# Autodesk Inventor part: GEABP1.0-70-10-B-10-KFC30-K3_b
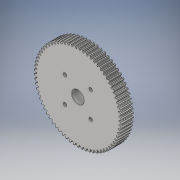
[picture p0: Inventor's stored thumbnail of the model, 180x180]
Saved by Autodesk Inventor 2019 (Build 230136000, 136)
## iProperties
Created: 2022-11
Part Number: GEABP1.0-70-10-B-10-KFC30-K3_b
Material: Generic
Catalog Web Link: www.cadenas.de
Description: GEABM, GEABMS, GEABMT, GEABP, GEABPS, GEABPT, GEABA, GEABAS, GEABAT_body-Plastic Spur Gears - Pressure Angle 20 Degrees, Module 0.5/0.8/1.0/1.5/2.0/2.5/3.0
Vendor: MISUMI
Document SubType Name: Modeling
Designer: psAdmin
Manufacturer: MISUMI
Mass: 48.5724 g
Surface Area: 144.734 cm^2
Volume: 48.5724 cm^3
Density: 1 g/cm^3
Appearance: PSOLRGB-175-175-175
Category: PARTsolutions
Company: MISUMI
Title: GEABP1.0-70-10-B-10-KFC30-K3
Author: Cadenas PARTsolutions
Comments: Plastic Spur Gears - Pressure Angle 20 Degrees, Module 0.5/0.8/1.0/1.5/2.0/2.5/3.0
PSOL_IDENT_0: {$CADENAS_DATA/23d-libs/misumi/metric/54_spur_gears/geabms20/geabms20.prj},408 {VTYP=3D},{NB=GEABP1.
PSOL_IDENT_1: 0-70-10-B-10-KFC30-K3_b},{LINA=GEABP1.0-70-10-B-10-KFC30-K3},{NN=GEABM, GEABMS, GEABMT, GEABP, GEABP
PSOL_IDENT_2: S, GEABPT, GEABA, GEABAS, GEABAT_body},{DATE=17.10.2022 23:48:33},{GEOMDATE=14.09.2022 05:11:00},{VE
PSOL_IDENT_3: RSION=},{LINEID=30},{WBVAR=MATSG,MATCR,NT,B,TS,PS,ALT1,ALT2,TPC,ALT11,ALT10,BS,ALT3,Z,J,ALT4,Q,R,S,T
PSOL_IDENT_4: ,ALT5,LFC,LTC,MALT5,ALT6,KFC,KTC,K},{WBNUMERIC=NT,B,BS,Z,J,Q,R,S,T,LFC,LTC,KFC,KTC,K}  {NB=GEABP1.0-
PSOL_IDENT_5: 70-10-B-10-KFC30-K3_b},{LINA=GEABP1.0-70-10-B-10-KFC30-K3},{KT=DUMMY},{PN=GEABP1.0-70-10-B-10-KFC30-
PSOL_IDENT_6: K3},{TYPE=GEABP},{MATSG=PW},{MATSGALG='MCN','MC Nylon','PW','Polyacetal White','PB','Polyacetal Blue'
PSOL_IDENT_7: },{MATCR=},{MATCRALG='','-','S45C','1045 Carbon Steel','SUS304','304 Stainless Steel'},{MOD=1.0},{MO
PSOL_IDENT_8: D1=1.0},{NT=70},{NTALG=15,16,18,20,22,24,25,26,28,30,32,35,36,40,45,48,50,55,60,70,75,80,90,100,120}
PSOL_IDENT_9: ,{B=10},{BALG=10,15},{TS=B},{TSALG='A','A','B','B'},{TSPN=-B},{PS=10},{PSALG='10','10','11','11','12'
PSOL_IDENT_10: ,'12','13','13','14','14','15','15','16','16','17','17','18','18','19','19','20','20','21','21','22'
PSOL_IDENT_11: ,'22','23','23','24','24','25','25','26','26','27','27','28','28'},{PSCRL='10','10','11','11','12','
PSOL_IDENT_12: 12','13','13','14','14','15','15','16','16','17','17','18','18','19','19','20','20','21','21','22','
PSOL_IDENT_13: 22','23','23','24','24','25','25','26','26','27','27','28','28'},{PSCRW='10','10','12','12','15','15'
PSOL_IDENT_14: ,'20','20'},{DD=70.0},{DD05=35},{DD08=56},{DD10=70},{DD15=105},{DD20=0},{DD25=0},{DD30=0},{D=72.0},{
PSOL_IDENT_15: D05=36},{D08=57.6},{D10=72},{D15=108},{D20=0},{D25=0},{D30=0},{G=67.50},{G05=33.75},{G08=54},{G10=67
PSOL_IDENT_16: .5},{G15=101.25},{G20=0},{G25=0},{G30=0},{H=40.0},{L=20},{LL1=10},{LL2=4.0},{M=M4},{M3D=4},{P=10.00}
PSOL_IDENT_17: ,{DD1=0},{CIFR=15},{CIFM=4},{CIFK=0},{CIFTAP=1},{ALT1=},{ALT1ALG='','w/o Set Screw','KC90','with KC9
PSOL_IDENT_18: 0 (Set Screw)','KC120','with KC120 (Set Screw)'},{ALT1PN=},{ALT2=},{ALT2ALG='','w/o TPC (Tapped Hole
PSOL_IDENT_19: Dimension)','TPC','with TPC (Tapped Hole Dimension)'},{TPC=N/A},{TPCALG='N/A'},{ALT2PN=},{KC=0},{AL
PSOL_IDENT_20: T11=},{ALT11ALG='', 'w/o GBA (Gear bottom adjustment of phase focus)', 'GBA', 'with GBA (Gear bottom
PSOL_IDENT_21: adjustment of phase focus)' },{ALT11PN=},{DEG=0},{ALT10=},{ALT10ALG= '','w/o BS (Boss Cut)','BS','w
PSOL_IDENT_22: ith BS (Boss Cut)' },{ALT10PN=},{BS=0.0},{BSALG=0},{BSMIN=7},{BSMINALG=7.000},{BSMAX=10},{LL13D=10},
PSOL_IDENT_23: {LL23D=16},{LBS=20},{ALT3=},{ALT3ALG= '','w/o Stepped Hole','DHL','with DHL (Stepped Hole)','DHR','w
PSOL_IDENT_24: ith DHR (Stepped Hole)' },{ALT3PN=},{ZJPN=},{ALT31=1},{ALT32=1},{Z=0},{ZALG=0},{ZMINL=12},{ZMAXL=63}
PSOL_IDENT_25: ,{ZMINR=12},{ZMAXR=36},{ZPN=},{J=0.0},{JALG=0},{JMIN=2},{JMAX=0},{JPN=},{ALT4=},{ALT4ALG= '','w/o WD
PSOL_IDENT_26: H (Both Ends Stepped Hole)','WDH','with WDH (Both Ends Stepped Hole)' },{ALT4PN=},{QRSTPN=},{LB=20.0
PSOL_IDENT_27: 00},{Q=0},{QALG=0},{QMIN=12},{QMAX=36},{QPN=},{R=0},{RALG=0},{RMIN=12},{RMAX=36},{RPN=},{S=0},{SALG=
PSOL_IDENT_28: 0},{SMIN=3},{SMAX=14},{SPN=},{T=0},{TALG=0},{TMIN=3},{TMAX=0},{TPN=},{ALT5=},{ALT5ALG= '','Not appli
PSOL_IDENT_29: cable' },{LFC=0},{LFCALG=0},{LTC=0},{LTCALG=0},{LPCDMIN=18},{LPCDMAX=60},{LCMAX=63},{MALT5=N/A},{MAL
PSOL_IDENT_30: T5ALG= 'N/A' },{LCMAX2=60},{C=0.0},{ALT5PN=},{ALT6=KFC},{ALT6ALG= '','w/o Side Through Hole','KFC','
PSOL_IDENT_31: with KFC (Side Through Hole)','KTC','with KTC (Side Through Hole)' },{ALT6PN=-KFC},{KFTCPN=30-K3},{K
PSOL_IDENT_32: FC=30},{KFCALG=[17:33/1],[47:60/1]},{KFCPN=30},{KTC=0},{KTCALG=[0]},{KTCPN=},{KPCDMIN1=17},{KPCDMAX1=
PSOL_IDENT_33: 33},{KPCDMIN2=47},{KPCDMAX2=60},{K=3.0},{KALG=[3:6/0.5]},{KPCD=30},{KPN=-K3},{SCREW=4},{SCREWL=3},{A
PSOL_IDENT_34: G=0},{PCD=30},{SHN=4},{SHDEG1=45},{SHDEG2=90},{PZQRDD2=10},{D1=1.285714},{D2=2.571429},{D3=20},{D4=0
PSOL_IDENT_35: .1},{D5=11.666667},{D6=10.769231},{D7=0.85},{D8=0.5},{D9=0.82917},{S1=15},{S2=0.5},{KR=15}
NB: GEABP1.0-70-10-B-10-KFC30-K3_b
NN: GEABM, GEABMS, GEABMT, GEABP, GEABPS, GEABPT, GEABA, GEABAS, GEABAT_body
NT: 70
NBSYN: $PN._b
LINA: GEABP1.0-70-10-B-10-KFC30-K3
CATALOG: Misumi
PN: GEABP1.0-70-10-B-10-KFC30-K3
MATSG: Polyacetal White
MATCR: -
MOD: 1.0
B: 10
TS: B
PS: 10
DD: 70
D: 72
G: 67.5
H: 40
L: 20
LL1: 10
LL2: 4
M: M4
DD1: 0
ALT1: w/o Set Screw
ALT2: w/o TPC (Tapped Hole Dimension)
TPC: N/A
ALT11: w/o GBA (Gear bottom adjustment of phase focus)
ALT10: w/o BS (Boss Cut)
BS: 0
ALT3: w/o Stepped Hole
Z: 0
J: 0
ALT4: w/o WDH (Both Ends Stepped Hole)
Q: 0
R: 0
S: 0
T: 0
ALT5: Not applicable
LFC: 0
LTC: 0
MALT5: N/A
C: 0
ALT6: with KFC (Side Through Hole)
KFC: 30
KTC: 0
K: 3
SUPPLIER: MISUMI
ARTICLENO: GEABP1.0-70-10-B-10-KFC30-K3_b
BOMINFO: GEABP1.0-70-10-B-10-KFC30-K3
CREATOR: CADENAS GmbH
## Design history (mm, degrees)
sketch "Sketch_2"
  geometry: L1 (0, -500)-(0, 500); L2 (0, 0)-(35.5, 0); L3 (35.5, 0)-(38, -0.67); L4 (38, -0.67)-(38, -9.33); L5 (38, -9.33)-(35.5, -10); L6 (35.5, -10)-(20, -10); L7 (20, -10)-(20, -19.7); L8 (20, -19.7)-(19.7, -20); L9 (19.7, -20)-(0, -20); L10 (0, -20)-(0, 0)
  constraints: 20 end point
revolve "Revolution1" sketch "Sketch_2" stored, may be unused: angle "d0" = 360 deg
sketch "_____12"
  geometry: C1 r 144 at (0, 0); A1 r 0.1 centre (-35.877, 1.285) between (-35.977, 1.288) and (-35.921, 1.195); A2 r 11.667 centre (-30.756, 11.656) between (-35.921, 1.195) and (-34.991, 0.785); A3 r 0.829 centre (-34.69, 1.558) between (-34.991, 0.785) and (-34.876, 0.75); A4 r 10.769 centre (-37.286, -9.746) between (-34.102, 0.542) and (-34.876, 0.75); A5 r 0.5 centre (-34.25, 0.064) between (-33.75, 0.063) and (-34.102, 0.542); A6 r 33.75 centre (0, 0) between (-33.75, 0.063) and (-33.75, -0.063); A7 r 0.5 centre (-34.25, -0.064) between (-34.102, -0.542) and (-33.75, -0.063); A8 r 10.769 centre (-37.286, 9.746) between (-34.876, -0.75) and (-34.102, -0.542); A9 r 0.829 centre (-34.69, -1.558) between (-34.876, -0.75) and (-34.991, -0.785); A10 r 11.667 centre (-30.756, -11.656) between (-34.991, -0.785) and (-35.921, -1.195); A11 r 0.1 centre (-35.877, -1.285) between (-35.921, -1.195) and (-35.977, -1.288); A12 r 36 centre (0, 0) between (-35.977, -1.288) and (-35.948, -1.942); A13 r 0.1 centre (-35.848, -1.936) between (-35.948, -1.942) and (-35.884, -2.03); A14 r 11.667 centre (-31.677, 8.852) between (-35.884, -2.03) and (-34.921, -2.354); A15 r 0.829 centre (-34.69, -1.558) between (-34.921, -2.354) and (-34.802, -2.379); A16 r 10.769 centre (-36.262, -13.049) between (-34.013, -2.517) and (-34.802, -2.379); A17 r 0.5 centre (-34.118, -3.006) between (-33.62, -2.963) and (-34.013, -2.517); A18 r 33.75 centre (0, 0) between (-33.62, -2.963) and (-33.608, -3.088); A19 r 0.5 centre (-34.106, -3.134) between (-33.916, -3.596) and (-33.608, -3.088); A20 r 10.769 centre (-38.009, 6.365) between (-34.668, -3.873) and (-33.916, -3.596); A21 r 0.829 centre (-34.411, -4.661) between (-34.668, -3.873) and (-34.78, -3.919); A22 r 11.667 centre (-29.587, -14.366) between (-34.78, -3.919) and (-35.67, -4.41); A23 r 0.1 centre (-35.617, -4.496) between (-35.67, -4.41) and (-35.717, -4.508); A24 r 36 centre (0, 0) between (-35.717, -4.508) and (-35.629, -5.156); A25 r 0.1 centre (-35.53, -5.142) between (-35.629, -5.156) and (-35.557, -5.238); A26 r 11.667 centre (-32.343, 5.977) between (-35.557, -5.238) and (-34.569, -5.475); A27 r 0.829 centre (-34.411, -4.661) between (-34.569, -5.475) and (-34.449, -5.49); A28 r 10.769 centre (-34.946, -16.247) between (-33.651, -5.556) and (-34.449, -5.49); A29 r 0.5 centre (-33.711, -6.053) between (-33.219, -5.964) and (-33.651, -5.556); A30 r 33.75 centre (0, 0) between (-33.219, -5.964) and (-33.196, -6.088); A31 r 0.5 centre (-33.688, -6.178) between (-33.457, -6.622) and (-33.196, -6.088); A32 r 10.769 centre (-38.427, 2.932) between (-34.181, -6.965) and (-33.457, -6.622); A33 r 0.829 centre (-33.855, -7.727) between (-34.181, -6.965) and (-34.289, -7.021); A34 r 11.667 centre (-28.18, -16.96) between (-34.289, -7.021) and (-35.131, -7.59); A35 r 0.1 centre (-35.071, -7.67) between (-35.131, -7.59) and (-35.169, -7.692); A36 r 36 centre (0, 0) between (-35.169, -7.692) and (-35.023, -8.329); A37 r 0.1 centre (-34.926, -8.306) between (-35.023, -8.329) and (-34.945, -8.404); A38 r 11.667 centre (-32.749, 3.054) between (-34.945, -8.404) and (-33.939, -8.552); A39 r 0.829 centre (-33.855, -7.727) between (-33.939, -8.552) and (-33.818, -8.555); A40 r 10.769 centre (-33.349, -19.314) between (-33.017, -8.55) and (-33.818, -8.555); A41 r 0.5 centre (-33.033, -9.05) between (-32.55, -8.918) and (-33.017, -8.55); A42 r 33.75 centre (0, 0) between (-32.55, -8.918) and (-32.517, -9.039); A43 r 0.5 centre (-32.999, -9.173) between (-32.729, -9.594) and (-32.517, -9.039); A44 r 10.769 centre (-38.535, -0.524) between (-33.419, -10.001) and (-32.729, -9.594); A45 r 0.829 centre (-33.026, -10.731) between (-33.419, -10.001) and (-33.521, -10.066); A46 r 11.667 centre (-26.547, -19.418) between (-33.521, -10.066) and (-34.309, -10.709); A47 r 0.1 centre (-34.242, -10.783) between (-34.309, -10.709) and (-34.338, -10.813); A48 r 36 centre (0, 0) between (-34.338, -10.813) and (-34.136, -11.435); A49 r 0.1 centre (-34.041, -11.403) between (-34.136, -11.435) and (-34.051, -11.503); A50 r 11.667 centre (-32.89, 0.106) between (-34.051, -11.503) and (-33.036, -11.56); A51 r 0.829 centre (-33.026, -10.731) between (-33.036, -11.56) and (-32.915, -11.552); A52 r 10.769 centre (-31.484, -22.226) between (-32.118, -11.476) and (-32.915, -11.552); A53 r 0.5 centre (-32.088, -11.975) between (-31.62, -11.8) and (-32.118, -11.476); A54 r 33.75 centre (0, 0) between (-31.62, -11.8) and (-31.576, -11.918); A55 r 0.5 centre (-32.044, -12.094) between (-31.737, -12.49) and (-31.576, -11.918); A56 r 10.769 centre (-38.333, -3.977) between (-32.388, -12.956) and (-31.737, -12.49); A57 r 0.829 centre (-31.931, -13.648) between (-32.388, -12.956) and (-32.484, -13.03); A58 r 11.667 centre (-24.699, -21.72) between (-32.484, -13.03) and (-33.211, -13.741); A59 r 0.1 centre (-33.138, -13.809) between (-33.211, -13.741) and (-33.23, -13.848); A60 r 36 centre (0, 0) between (-33.23, -13.848) and (-32.973, -14.449); A61 r 0.1 centre (-32.882, -14.409) between (-32.973, -14.449) and (-32.883, -14.509); A62 r 11.667 centre (-32.768, -2.843) between (-32.883, -14.509) and (-31.867, -14.475); A63 r 0.829 centre (-31.931, -13.648) between (-31.867, -14.475) and (-31.747, -14.456); A64 r 10.769 centre (-29.365, -24.959) between (-30.96, -14.308) and (-31.747, -14.456)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; 1 further point
  constraints: 1680 point on circle, 841 centre point
extrude "Extrusion1" cut sketch "_____12" distance "d1" = 10; taper "d2" = 0 deg
sketch "Sketch3"
  geometry: 1 further point
hole "Hole1" sketch "Sketch3" at (0, 0) diameter "d3" = 10; stored, may be unused: countersink angle "d7" = 90 deg, drill point angle "d9" = 0 deg; dims "d4" = 6, "d5" = 4, "d6" = 2, "d8" = 20
sketch "_____5"
  geometry: L1 (500, 0)-(-500, 0); L2 (19.7, 5)-(20, 5); L3 (20, 5)-(20, 5.3); L4 (20, 5.3)-(19.7, 5)
  constraints: 8 end point
revolve "Revolution2" sketch "_____5" stored, may be unused: angle "d10" = 360 deg
sketch "_____13"
  geometry: L1 (500, 0)-(-500, 0); L2 (0, 5.3)-(0, 5); L3 (0, 5)-(0.3, 5); L4 (0.3, 5)-(0, 5.3)
  constraints: 8 end point
revolve "Revolution3" sketch "_____13" stored, may be unused: angle "d11" = 360 deg
sketch "Sketch_4"
  geometry: L1 (0, 20)-(0, 0); L2 (0, 0)-(-1.621, 0); L3 (-1.621, 0)-(-1.621, 19.621); L4 (-1.621, 19.621)-(-2, 20); L5 (-2, 20)-(0, 20); L6 (0, 20)-(0, 0)
  constraints: 12 end point
revolve "Revolution4" sketch "Sketch_4" stored, may be unused: angle "d12" = 360 deg
thread "Thread1" dims "d13" = 14.621, "d14" = 0
sketch "Sketch7"
  geometry: 1 further point
hole "Hole2" sketch "Sketch7" at (-10.607, 10.607) diameter "d15" = 3; stored, may be unused: countersink angle "d19" = 90 deg, drill point angle "d21" = 0 deg; dims "d16" = 6, "d17" = 4, "d18" = 2, "d20" = 20
pattern_linear "Rectangular Pattern1" dims "d24" = 21.2132, "d27" = 21.2132
node "gear_to_screw_XY"
node "gear_to_screw_YZ"
node "gear_to_screw_ZX"
node "gear_to_screw_X"
node "gear_to_screw_Y"
node "gear_to_screw_Z"
node "gear_to_screw_Center"
body "Solid1"
